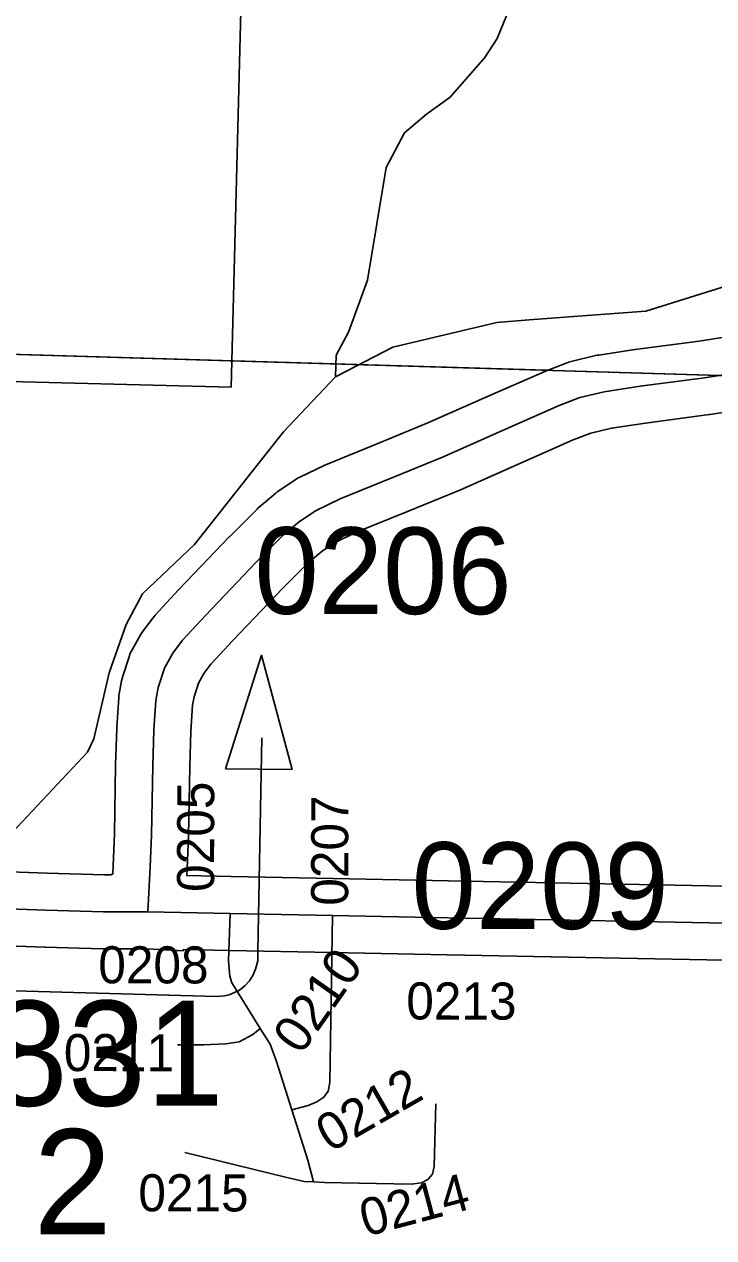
# Model space of a CAD drawing. Extents: x -132.8 to -73.3, y -60 to -26.
# Drawn here: x -117.558 to -117, y -51.155 to -50.173 of the extents above; entities that cross this region are included whole.
import ezdxf

# ---------------------------------------------------------------- set-up
doc = ezdxf.new("R2010")
doc.units = 0
for name, color, linetype in [('tdCoCorpBndry', 7, 'Continuous'), ('tdCoDirctArrow', 7, 'Continuous'), ('tdCoHydroRiver', 7, 'Continuous'), ('tdCoSecRdNmbr', 7, 'Continuous'), ('tdCoSecRteBand', 7, 'Continuous'), ('tdCoSecRteCL', 7, 'Continuous'), ('tdCoSectLine', 7, 'Continuous'), ('tdCoSectLinePart', 7, 'Continuous'), ('tdCoStrucSecCoName', 7, 'Continuous'), ('tdCoStrucSecFHWANum', 7, 'Continuous'), ('tdCoSurfAsphaltUnbanded', 7, 'Continuous'), ('tdCoSurfBitum', 7, 'Continuous'), ('tdCoSurfConc', 7, 'Continuous'), ('tdCoTwpBndry', 7, 'Continuous'), ('tdCoTwpBndryShd', 7, 'Continuous')]:
    doc.layers.add(name, color=color, linetype=linetype)

msp = doc.modelspace()

# ---------------------------------------------------------------- linework, layer by layer
at = {"layer": 'tdCoCorpBndry'}
msp.add_lwpolyline([(-117.3811, -50.08845), (-117.39079, -50.46666), (-117.71793, -50.45828), (-117.71735, -50.4357), (-117.9419, -50.429), (-118.1899, -50.4203), (-118.19752, -50.6254), (-118.94769, -50.61042)], dxfattribs=at)
at = {"layer": 'tdCoDirctArrow'}
msp.add_lwpolyline([(-117.39539, -50.77556), (-117.36626, -50.68368), (-117.3415, -50.77612)], close=True, dxfattribs=at)
msp.add_lwpolyline([(-117.86483, -50.947), (-117.40276, -50.95993), (-117.39629, -50.95934), (-117.39254, -50.95854), (-117.38813, -50.95667), (-117.38412, -50.95466), (-117.37984, -50.95131), (-117.37609, -50.94716), (-117.37328, -50.94275), (-117.37101, -50.9378), (-117.36927, -50.9311), (-117.36932, -50.92353), (-117.36596, -50.75051)], dxfattribs=at)
at = {"layer": 'tdCoHydroRiver'}
for points in [[(-117.16537, -50.15949), (-117.17552, -50.18446), (-117.18557, -50.19979)], [(-117.18557, -50.19979), (-117.21344, -50.232), (-117.23275, -50.24568), (-117.25052, -50.26098), (-117.26548, -50.28898), (-117.28054, -50.38008), (-117.29588, -50.42227), (-117.30585, -50.44093), (-117.30632, -50.45827)], [(-116.49777, -50.26796), (-116.50569, -50.26933), (-116.53121, -50.27973), (-116.68355, -50.31213), (-116.75832, -50.33546), (-116.83346, -50.37299), (-116.84781, -50.37894), (-116.9757, -50.38041), (-117.05524, -50.4052), (-117.10268, -50.40872), (-117.14947, -50.41214)], [(-117.14947, -50.41214), (-117.17571, -50.41446), (-117.2599, -50.43428), (-117.30632, -50.45827)], [(-117.30632, -50.45827), (-117.34855, -50.50289), (-117.42044, -50.59404), (-117.46255, -50.63393), (-117.47584, -50.65882), (-117.48952, -50.69789), (-117.50199, -50.7512), (-117.50702, -50.76211), (-117.65324, -50.91753), (-117.70071, -50.98094), (-117.72364, -51.01187), (-117.74806, -51.03962), (-117.81697, -51.13716), (-117.9356, -51.32329), (-117.95529, -51.35117), (-117.95857, -51.35581), (-118.06869, -51.51851), (-118.07592, -51.55303), (-118.08584, -51.8052), (-118.09121, -51.82873), (-118.09367, -51.86179), (-118.07405, -51.89545), (-118.07229, -51.94757)]]:
    msp.add_lwpolyline(points, dxfattribs=at)
at = {"layer": 'tdCoSecRteBand'}
for points in [[(-117.58546, -50.85836), (-117.53978, -50.86008), (-117.49373, -50.86129), (-117.48758, -50.8613), (-117.48757, -50.86076), (-117.4867, -50.86078), (-117.48636, -50.85374), (-117.48529, -50.8281), (-117.48436, -50.77276), (-117.48436, -50.77259), (-117.48435, -50.77242), (-117.48352, -50.74309), (-117.48351, -50.7425), (-117.48347, -50.74191), (-117.48187, -50.71824), (-117.48175, -50.71651), (-117.48144, -50.71481), (-117.47952, -50.70445), (-117.47917, -50.70254), (-117.47857, -50.7007), (-117.47348, -50.6849), (-117.47255, -50.682), (-117.47106, -50.67936), (-117.46422, -50.66724), (-117.46325, -50.66552), (-117.46205, -50.66393), (-117.45422, -50.65354), (-117.45329, -50.65231), (-117.45224, -50.65117), (-117.43337, -50.63086), (-117.43323, -50.63071), (-117.43309, -50.63056), (-117.39216, -50.5877), (-117.39192, -50.58745), (-117.39167, -50.5872), (-117.36985, -50.56539), (-117.36895, -50.56449), (-117.36797, -50.56367), (-117.35472, -50.55251), (-117.3535, -50.55148), (-117.35217, -50.55058), (-117.33891, -50.54164), (-117.33711, -50.54042), (-117.33515, -50.53948), (-117.31548, -50.53001), (-117.31463, -50.5296), (-117.31376, -50.52924), (-117.27076, -50.51178), (-117.23159, -50.49571), (-117.17664, -50.47143), (-117.17662, -50.47142), (-117.1766, -50.47141), (-117.1375, -50.45419), (-117.1369, -50.45393), (-117.13628, -50.45369), (-117.11955, -50.44719), (-117.11767, -50.44645), (-117.1157, -50.44598), (-117.09576, -50.44119), (-117.09448, -50.44088), (-117.09319, -50.44069), (-117.06413, -50.43634), (-117.06389, -50.43631), (-117.06366, -50.43628), (-117.012, -50.42939), (-116.96773, -50.42254)], [(-116.95867, -50.48185), (-117.00314, -50.48873), (-117.00344, -50.48878), (-117.00375, -50.48882), (-117.05549, -50.49572), (-117.08302, -50.49984), (-117.09971, -50.50385), (-117.11393, -50.50937), (-117.1524, -50.52631), (-117.20771, -50.55076), (-117.20808, -50.55092), (-117.20845, -50.55108), (-117.24805, -50.56731), (-117.24809, -50.56733), (-117.24814, -50.56735), (-117.2903, -50.58447), (-117.30716, -50.59259), (-117.31729, -50.59943), (-117.32834, -50.60873), (-117.34901, -50.62939), (-117.38955, -50.67185), (-117.40723, -50.69088), (-117.41294, -50.69846), (-117.41731, -50.70619), (-117.42087, -50.71726), (-117.42212, -50.72401), (-117.42356, -50.74537), (-117.42437, -50.77394), (-117.4253, -50.82948), (-117.42531, -50.82985), (-117.42532, -50.83023), (-117.42641, -50.85636), (-117.42642, -50.85647), (-117.42642, -50.85657), (-117.42669, -50.86196), (-117.39096, -50.86267), (-117.30817, -50.8643), (-117.21486, -50.86615), (-116.98995, -50.87048)], [(-116.99175, -50.93046), (-117.21602, -50.92614), (-117.21603, -50.92614), (-117.21604, -50.92614), (-117.30935, -50.92429), (-117.39214, -50.92266), (-117.42963, -50.92192), (-117.42967, -50.92278), (-117.45892, -50.92135), (-117.49419, -50.92129), (-117.49457, -50.92129), (-117.49494, -50.92128), (-117.54153, -50.92005), (-117.5417, -50.92005), (-117.54187, -50.92004), (-117.58763, -50.91832)]]:
    msp.add_lwpolyline(points, dxfattribs=at)
at = {"layer": 'tdCoSecRteCL'}
for p, q in [((-117.45816, -50.89135), (-117.39155, -50.89266)), ((-117.39155, -50.89266), (-117.30876, -50.8943))]:
    msp.add_line(p, q, dxfattribs=at)
for points in [[(-117.45816, -50.89135), (-117.45639, -50.85511), (-117.4553, -50.82897), (-117.45436, -50.77327), (-117.45353, -50.74393), (-117.45194, -50.72026), (-117.45002, -50.7099), (-117.44493, -50.6941), (-117.43809, -50.68199), (-117.43026, -50.67159), (-117.41139, -50.65128), (-117.37046, -50.60842), (-117.34864, -50.58661), (-117.3354, -50.57545), (-117.32213, -50.56651), (-117.30247, -50.55704), (-117.25943, -50.53955), (-117.21983, -50.52332), (-117.16451, -50.49887), (-117.12541, -50.48165), (-117.10869, -50.47515), (-117.08875, -50.47036), (-117.05969, -50.46601), (-117.00772, -50.45908), (-116.96315, -50.45219)], [(-117.95959, -50.87235), (-117.93099, -50.87417), (-117.86244, -50.87848), (-117.81141, -50.88141), (-117.76901, -50.88291), (-117.71773, -50.8851), (-117.6603, -50.88602), (-117.58659, -50.88834), (-117.54074, -50.89006), (-117.49415, -50.89129), (-117.45816, -50.89135)], [(-117.36726, -50.98575), (-117.37734, -50.96945), (-117.38573, -50.95613), (-117.39017, -50.94873), (-117.39189, -50.94331), (-117.39288, -50.93098), (-117.39155, -50.89266)], [(-117.34169, -51.05159), (-117.32851, -51.04812), (-117.32136, -51.04516), (-117.31594, -51.04121), (-117.31224, -51.03653), (-117.31101, -51.02937), (-117.30876, -50.8943)], [(-117.30876, -50.8943), (-117.21545, -50.89614), (-116.96086, -50.90105)], [(-117.43431, -50.99904), (-117.41335, -50.99904), (-117.3951, -50.9983), (-117.38449, -50.99657), (-117.3734, -50.99066), (-117.36726, -50.98575)], [(-117.34169, -51.05159), (-117.35416, -51.01236), (-117.35934, -50.99855), (-117.36726, -50.98575)], [(-117.32426, -51.10997), (-117.3152, -51.11051), (-117.24516, -51.11174), (-117.23678, -51.11075), (-117.2316, -51.10804), (-117.2279, -51.1036), (-117.22642, -51.09744), (-117.22519, -51.04664)], [(-117.32426, -51.10997), (-117.32876, -51.09226), (-117.34169, -51.05159)], [(-117.42839, -51.08609), (-117.34578, -51.10631), (-117.33172, -51.10952), (-117.32426, -51.10997)]]:
    msp.add_lwpolyline(points, dxfattribs=at)
at = {"layer": 'tdCoSectLine'}
msp.add_lwpolyline([(-117.94228, -50.429), (-116.94954, -50.45863)], dxfattribs=at)
at = {"layer": 'tdCoSectLinePart'}
msp.add_lwpolyline([(-117.39063, -50.44546), (-117.13499, -50.45309)], dxfattribs=at)
at = {"layer": 'tdCoSurfAsphaltUnbanded'}
for points in [[(-117.36726, -50.98575), (-117.37734, -50.96945), (-117.38573, -50.95613), (-117.39017, -50.94873), (-117.39189, -50.94331), (-117.39288, -50.93098), (-117.39155, -50.89266)], [(-117.34169, -51.05159), (-117.32851, -51.04812), (-117.32136, -51.04516), (-117.31594, -51.04121), (-117.31224, -51.03653), (-117.31101, -51.02937), (-117.30876, -50.8943)], [(-117.43431, -50.99904), (-117.41335, -50.99904), (-117.3951, -50.9983), (-117.38449, -50.99657), (-117.3734, -50.99066), (-117.36726, -50.98575)], [(-117.34169, -51.05159), (-117.35416, -51.01236), (-117.35934, -50.99855), (-117.36726, -50.98575)], [(-117.32426, -51.10997), (-117.3152, -51.11051), (-117.24516, -51.11174), (-117.23678, -51.11075), (-117.2316, -51.10804), (-117.2279, -51.1036), (-117.22642, -51.09744), (-117.22519, -51.04664)], [(-117.32426, -51.10997), (-117.32876, -51.09226), (-117.34169, -51.05159)], [(-117.42839, -51.08609), (-117.34578, -51.10631), (-117.33172, -51.10952), (-117.32426, -51.10997)]]:
    msp.add_lwpolyline(points, dxfattribs=at)
at = {"layer": 'tdCoSurfBitum'}
msp.add_lwpolyline([(-116.96086, -50.90105), (-117.21545, -50.89614), (-117.30876, -50.8943), (-117.39155, -50.89266), (-117.45816, -50.89135), (-117.49415, -50.89129), (-117.54074, -50.89006), (-117.58659, -50.88834), (-117.6603, -50.88602), (-117.71773, -50.8851), (-117.76901, -50.88291), (-117.81141, -50.88141), (-117.86244, -50.87848), (-117.93099, -50.87417), (-117.95959, -50.87235)], dxfattribs=at)
at = {"layer": 'tdCoSurfConc'}
msp.add_lwpolyline([(-117.45816, -50.89135), (-117.45639, -50.85511), (-117.4553, -50.82897), (-117.45436, -50.77327), (-117.45353, -50.74393), (-117.45194, -50.72026), (-117.45002, -50.7099), (-117.44493, -50.6941), (-117.43809, -50.68199), (-117.43026, -50.67159), (-117.41139, -50.65128), (-117.37046, -50.60842), (-117.34864, -50.58661), (-117.3354, -50.57545), (-117.32213, -50.56651), (-117.30247, -50.55704), (-117.25943, -50.53955), (-117.21983, -50.52332), (-117.16451, -50.49887), (-117.12541, -50.48165), (-117.10869, -50.47515), (-117.08875, -50.47036), (-117.05969, -50.46601), (-117.00772, -50.45908), (-116.96315, -50.45219)], dxfattribs=at)
at = {"layer": 'tdCoTwpBndry'}
msp.add_lwpolyline([(-118.90673, -50.39514), (-117.94228, -50.429), (-117.1351, -50.45309)], dxfattribs=at)
at = {"layer": 'tdCoTwpBndryShd'}
msp.add_lwpolyline([(-120.91911, -50.34667), (-120.42154, -50.3572), (-119.92398, -50.36772), (-119.43054, -50.38425), (-118.93694, -50.39408), (-117.94228, -50.429), (-116.94954, -50.45863), (-115.94944, -50.48304), (-114.99608, -50.51274), (-114.00114, -50.5352), (-112.98652, -50.56418), (-112.00171, -50.59566), (-111.00515, -50.62796), (-110.64057, -50.64274), (-110.0099, -50.65834), (-109.04664, -50.682), (-108.0484, -50.70573), (-107.05486, -50.73586), (-106.05865, -50.75809), (-105.06305, -50.78747), (-104.06669, -50.813)], dxfattribs=at)

# ---------------------------------------------------------------- texts
at = {"layer": 'tdCoSecRdNmbr'}
for s, height, rotation, p in [('0206', 0.07, 359.91187, (-117.37205, -50.65011)), ('0205', 0.03, 89.91229, (-117.40465, -50.87523)), ('0207', 0.03, 89.91237, (-117.29612, -50.8864)), ('0209', 0.07, 359.9122, (-117.24487, -50.90503)), ('0208', 0.03, 359.91229, (-117.49841, -50.94918)), ('0210', 0.03, 54.9122, (-117.33431, -51.00799)), ('0213', 0.03, 359.91202, (-117.24908, -50.97845)), ('0211', 0.03, 359.91231, (-117.5263, -51.02024)), ('0212', 0.03, 29.91216, (-117.31073, -51.08653)), ('0215', 0.03, 359.91236, (-117.46597, -51.13371)), ('0214', 0.03, 14.91241, (-117.28197, -51.15442))]:
    msp.add_text(s, height=height, rotation=rotation, dxfattribs=at).set_placement(p)
at = {"layer": 'tdCoStrucSecCoName'}
msp.add_text('LE 2', height=0.085, dxfattribs=at).set_placement((-117.72145, -51.15228))
at = {"layer": 'tdCoStrucSecFHWANum'}
msp.add_text('284831', height=0.085, dxfattribs=at).set_placement((-117.77599, -51.0483))

doc.saveas('drawing.dxf')
